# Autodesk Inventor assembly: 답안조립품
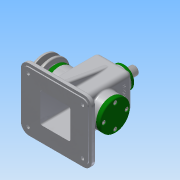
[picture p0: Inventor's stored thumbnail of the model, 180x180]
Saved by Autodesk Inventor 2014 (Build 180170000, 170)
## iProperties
Created: 2015-12
Part Number: 답안조립품
Document SubType Name: Assembly
Designer: Administrator
Author: Administrator
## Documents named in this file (19)
- D:\451225V1015\답안조립품.iam
- D:\451225V1015\베어링 15 x 35 x 11.ipt
- D:\451225V1015\볼트 M3 x 8.ipt
- D:\451225V1015\볼트 M4 x 10.ipt
- D:\451225V1015\볼트 M6 x 12.ipt
- D:\451225V1015\상부부시.ipt
- D:\451225V1015\슬라이드바.ipt
- D:\451225V1015\앞커버.ipt
- D:\451225V1015\오일실 15 25 7.ipt
- D:\451225V1015\와셔.ipt
- D:\451225V1015\키 5 x 5 x 14.ipt
- D:\451225V1015\편심축.ipt
- D:\451225V1015\V-벨트풀리.ipt
- D:\451225V1015\1-본체.ipt
- D:\451225V1015\고정핀.ipt
- D:\451225V1015\뒤커버.ipt
- D:\451225V1015\링크.ipt
- D:\451225V1015\멈춤링 6 x 5.ipt
- D:\451225V1015\멈춤링 15 x 1.ipt
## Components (16 placed, 6 different names)
1. ISO 4018 M6 x 12:1
2. V-벨트풀리:1
3. 1-본체:1
4. 고정핀:1 — 플러쉬:2
5. ISO 4762 M3 x 8:1
6. ISO 4762 M3 x 8:2
7. ISO 4762 M3 x 8:3
8. ISO 4762 M3 x 8:4
9. ISO 4762 M4 x 10:1
10. ISO 4762 M4 x 10:3
11. ISO 4762 M4 x 10:4
12. ISO 4762 M4 x 10:5
13. ISO 4762 M4 x 10:2
14. ISO 4762 M4 x 10:6
15. ISO 4762 M4 x 10:7
16. ISO 4762 M4 x 10:8
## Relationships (1: Flush 1)
- 플러쉬:2 [Flush]: 고정핀:1
